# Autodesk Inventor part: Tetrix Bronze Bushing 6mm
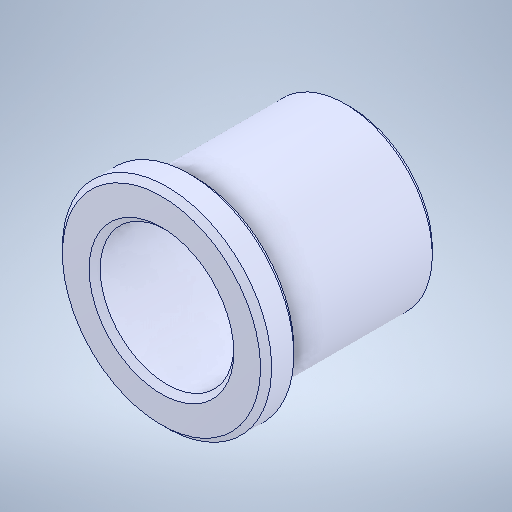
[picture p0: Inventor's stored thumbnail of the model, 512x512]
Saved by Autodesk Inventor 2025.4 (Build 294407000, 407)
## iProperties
Created: 2021-10
Part Number: Tetrix Bronze Bushing 6mm
Material: Genérico
Document SubType Name: Modeling
Designer: usuario
Density: 1 g/cm^3
Appearance: Valor por defecto
Author: usuario
Sending System: SolidWorks 2016
Last Author: LENOVO
Last Saved: 2021-10-26
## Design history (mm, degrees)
feature "Revolve1"
node "Plane1"
node "Sólido1"
